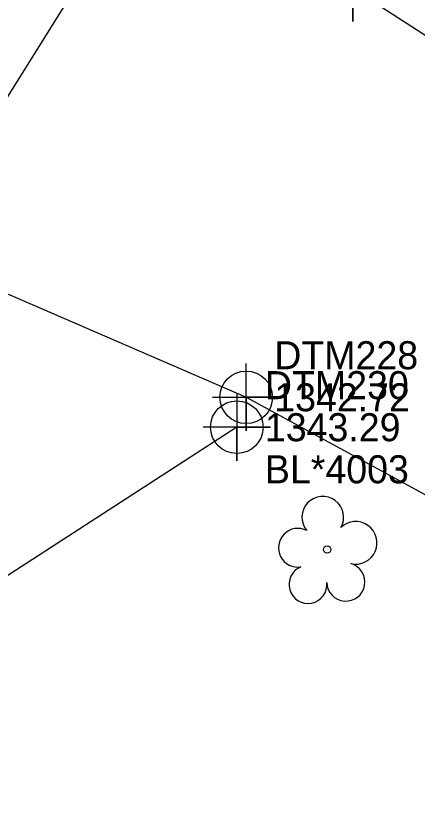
# Model space of a CAD drawing. Extents: x 1435573 to 1437263, y 981340 to 982884.
# Drawn here: x 1436200.8 to 1436236.5, y 982298.4 to 982369.2 of the extents above; entities that cross this region are included whole.
import ezdxf

# ---------------------------------------------------------------- set-up
doc = ezdxf.new("R2010")
doc.units = 0
for name, color, linetype in [('Exist DTM Drainline', 7, 'Continuous'), ('Exist DTM Drainline Cogo Comment', 7, 'Continuous'), ('Exist DTM Drainline Cogo Elevation', 7, 'Continuous'), ('Exist DTM Drainline Cogo Number', 7, 'Continuous'), ('Exist DTM Drainline Cogo Point CELL', 7, 'Continuous'), ('Exist Hydro Jurisdictional Stream or Body of Water', 7, 'Continuous'), ('Exist Hydro Stream or Body of Water Cogo Elevation', 7, 'Continuous'), ('Exist Hydro Stream or Body of Water Cogo Number', 7, 'Continuous'), ('Exist Hydro Stream or Body of Water Cogo Point CELL', 7, 'Continuous'), ('Exist Right of Way Line', 7, 'Continuous'), ('Exist Vegetation Tree CELL', 7, 'Continuous')]:
    doc.layers.add(name, color=color, linetype=linetype)

msp = doc.modelspace()

# ---------------------------------------------------------------- linework, layer by layer
at = {"layer": 'Exist DTM Drainline'}
msp.add_line((1436220.436, 982332.504), (1436178.925, 982305.614), dxfattribs=at)
at = {"layer": 'Exist DTM Drainline Cogo Point CELL'}
msp.add_lwpolyline([(1436220.436, 982335.504), (1436220.436, 982329.504), (1436220.436, 982332.504), (1436223.436, 982332.504), (1436217.436, 982332.504)], dxfattribs=at)
msp.add_circle((1436220.436, 982332.504), 2.344, dxfattribs=at)
at = {"layer": 'Exist Hydro Jurisdictional Stream or Body of Water'}
for points in [[(1436111.154, 982453.743), (1436137.021, 982423.293), (1436156.592, 982404.891), (1436183.389, 982389.762), (1436202.59, 982381.738), (1436230.764, 982371.656), (1436265.68, 982349.113), (1436287.963, 982335.568), (1436310.384, 982331.326), (1436342.495, 982321.193), (1436376.372, 982319.714), (1436409.657, 982315.499), (1436442.825, 982320.596), (1436463.486, 982320.372), (1436497.532, 982330.714), (1436550.332, 982336.593), (1436616.166, 982332.311)], [(1436091.982, 982443.751), (1436118.691, 982406.49), (1436146.126, 982381.568), (1436167.284, 982362.748), (1436182.899, 982351.8), (1436221.27, 982335.172), (1436252.295, 982318.284), (1436286.205, 982313.627), (1436313.861, 982303.985), (1436344.053, 982299.63), (1436382.914, 982293.643), (1436445.462, 982294.468), (1436493.305, 982296.219), (1436523.006, 982301.225), (1436526.678, 982304.851), (1436546.503, 982314.758), (1436602.72, 982314.242)]]:
    msp.add_lwpolyline(points, dxfattribs=at)
at = {"layer": 'Exist Hydro Stream or Body of Water Cogo Point CELL'}
for points in [[(1436227.764, 982371.656), (1436233.764, 982371.656), (1436230.764, 982371.656), (1436230.764, 982368.656), (1436230.764, 982374.656)], [(1436218.27, 982335.172), (1436224.27, 982335.172), (1436221.27, 982335.172), (1436221.27, 982332.172), (1436221.27, 982338.172)]]:
    msp.add_lwpolyline(points, dxfattribs=at)
msp.add_circle((1436221.27, 982335.172), 2.344, dxfattribs=at)
at = {"layer": 'Exist Right of Way Line'}
msp.add_line((1436183.124, 982334.928), (1436209.255, 982376.756), dxfattribs=at)
at = {"layer": 'Exist Vegetation Tree CELL'}
msp.add_line((1436228.476, 982321.605), (1436228.476, 982321.605), dxfattribs=at)
msp.add_circle((1436228.476, 982321.605), 0.326, dxfattribs=at)
for centre, radius, start, end in [((1436228.091, 982324.479), 1.856, 330.16508, 219.71335), ((1436231.025, 982322.194), 1.899, 257.1011, 134.19993), ((1436225.87, 982321.759), 1.727, 62.66361, 279.3457), ((1436230.148, 982318.706), 1.698, 181.28216, 74.55999), ((1436226.771, 982318.485), 1.689, 111.56708, 6.23104)]:
    msp.add_arc(centre, radius, start, end, dxfattribs=at)

# ---------------------------------------------------------------- texts
at = {"layer": 'Exist DTM Drainline Cogo Comment'}
msp.add_text('BL*4003', height=2.5, dxfattribs=at).set_placement((1436222.936, 982327.504))
at = {"layer": 'Exist DTM Drainline Cogo Elevation'}
msp.add_text('1343.29', height=2.5, dxfattribs=at).set_placement((1436222.936, 982331.254))
at = {"layer": 'Exist DTM Drainline Cogo Number'}
msp.add_text('DTM230', height=2.5, dxfattribs=at).set_placement((1436222.936, 982335.004))
at = {"layer": 'Exist Hydro Stream or Body of Water Cogo Elevation'}
msp.add_text('1342.72', height=2.5, dxfattribs=at).set_placement((1436223.77, 982333.922))
at = {"layer": 'Exist Hydro Stream or Body of Water Cogo Number'}
msp.add_text('DTM228', height=2.5, dxfattribs=at).set_placement((1436223.77, 982337.672))

doc.saveas('drawing.dxf')
